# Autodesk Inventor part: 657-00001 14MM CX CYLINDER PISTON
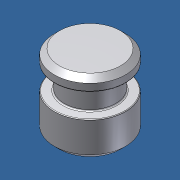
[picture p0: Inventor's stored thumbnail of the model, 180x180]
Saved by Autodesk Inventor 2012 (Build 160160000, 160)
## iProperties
Created: 2013-10
Part Number: 657-00001 14MM CX CYLINDER PISTON
Material: Default
Document SubType Name: Modeling
Designer: Admin
Density: 1 g/cm^3
Author: Admin
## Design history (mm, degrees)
node "657-00001 14MM CX CYLINDER PISTON1"
node "Base1"
body "Solid1"
